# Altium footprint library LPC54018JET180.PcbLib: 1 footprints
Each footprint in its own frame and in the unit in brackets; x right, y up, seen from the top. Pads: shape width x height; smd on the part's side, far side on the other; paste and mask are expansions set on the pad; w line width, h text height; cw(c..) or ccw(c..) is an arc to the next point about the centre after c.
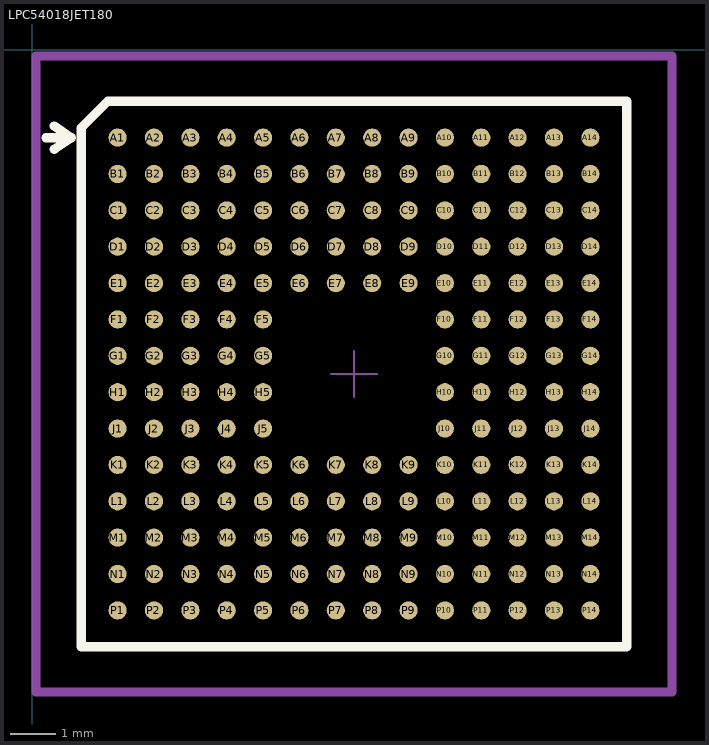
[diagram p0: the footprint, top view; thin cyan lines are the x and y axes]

## LPC54018JET180 [mm]
pads (180):
  round 0.4 smd: A1(1.876,-1.934) A2(2.676,-1.934) A3(3.476,-1.934) A4(4.276,-1.934) A5(5.076,-1.934) A6(5.876,-1.934) A7(6.676,-1.934) A8(7.476,-1.934) A9(8.276,-1.934) A10(9.076,-1.934) A11(9.876,-1.934) A12(10.676,-1.934) A13(11.476,-1.934) A14(12.276,-1.934) B1(1.876,-2.734) B2(2.676,-2.734) B3(3.476,-2.734) B4(4.276,-2.734) B5(5.076,-2.734) B6(5.876,-2.734) B7(6.676,-2.734) B8(7.476,-2.734) B9(8.276,-2.734) B10(9.076,-2.734) B11(9.876,-2.734) B12(10.676,-2.734) B13(11.476,-2.734) B14(12.276,-2.734) C1(1.876,-3.534) C2(2.676,-3.534) C3(3.476,-3.534) C4(4.276,-3.534) C5(5.076,-3.534) C6(5.876,-3.534) C7(6.676,-3.534) C8(7.476,-3.534) C9(8.276,-3.534) C10(9.076,-3.534) C11(9.876,-3.534) C12(10.676,-3.534) C13(11.476,-3.534) C14(12.276,-3.534) D1(1.876,-4.334) D2(2.676,-4.334) D3(3.476,-4.334) D4(4.276,-4.334) D5(5.076,-4.334) D6(5.876,-4.334) D7(6.676,-4.334) D8(7.476,-4.334) D9(8.276,-4.334) D10(9.076,-4.334) D11(9.876,-4.334) D12(10.676,-4.334) D13(11.476,-4.334) D14(12.276,-4.334) E1(1.876,-5.134) E2(2.676,-5.134) E3(3.476,-5.134) E4(4.276,-5.134) E5(5.076,-5.134) E6(5.876,-5.134) E7(6.676,-5.134) E8(7.476,-5.134) E9(8.276,-5.134) E10(9.076,-5.134) E11(9.876,-5.134) E12(10.676,-5.134) E13(11.476,-5.134) E14(12.276,-5.134) F1(1.876,-5.934) F2(2.676,-5.934) F3(3.476,-5.934) F4(4.276,-5.934) F5(5.076,-5.934) F10(9.076,-5.934) F11(9.876,-5.934) F12(10.676,-5.934) F13(11.476,-5.934) F14(12.276,-5.934) G1(1.876,-6.734) G2(2.676,-6.734) G3(3.476,-6.734) G4(4.276,-6.734) G5(5.076,-6.734) G10(9.076,-6.734) G11(9.876,-6.734) G12(10.676,-6.734) G13(11.476,-6.734) G14(12.276,-6.734) H1(1.876,-7.534) H2(2.676,-7.534) H3(3.476,-7.534) H4(4.276,-7.534) H5(5.076,-7.534) H10(9.076,-7.534) H11(9.876,-7.534) H12(10.676,-7.534) H13(11.476,-7.534) H14(12.276,-7.534) J1(1.876,-8.334) J2(2.676,-8.334) J3(3.476,-8.334) J4(4.276,-8.334) J5(5.076,-8.334) J10(9.076,-8.334) J11(9.876,-8.334) J12(10.676,-8.334) J13(11.476,-8.334) J14(12.276,-8.334) K1(1.876,-9.134) K2(2.676,-9.134) K3(3.476,-9.134) K4(4.276,-9.134) K5(5.076,-9.134) K6(5.876,-9.134) K7(6.676,-9.134) K8(7.476,-9.134) K9(8.276,-9.134) K10(9.076,-9.134) K11(9.876,-9.134) K12(10.676,-9.134) K13(11.476,-9.134) K14(12.276,-9.134) L1(1.876,-9.934) L2(2.676,-9.934) L3(3.476,-9.934) L4(4.276,-9.934) L5(5.076,-9.934) L6(5.876,-9.934) L7(6.676,-9.934) L8(7.476,-9.934) L9(8.276,-9.934) L10(9.076,-9.934) L11(9.876,-9.934) L12(10.676,-9.934) L13(11.476,-9.934) L14(12.276,-9.934) M1(1.876,-10.734) M2(2.676,-10.734) M3(3.476,-10.734) M4(4.276,-10.734) M5(5.076,-10.734) M6(5.876,-10.734) M7(6.676,-10.734) M8(7.476,-10.734) M9(8.276,-10.734) M10(9.076,-10.734) M11(9.876,-10.734) M12(10.676,-10.734) M13(11.476,-10.734) M14(12.276,-10.734) N1(1.876,-11.534) N2(2.676,-11.534) N3(3.476,-11.534) N4(4.276,-11.534) N5(5.076,-11.534) N6(5.876,-11.534) N7(6.676,-11.534) N8(7.476,-11.534) N9(8.276,-11.534) N10(9.076,-11.534) N11(9.876,-11.534) N12(10.676,-11.534) N13(11.476,-11.534) N14(12.276,-11.534) P1(1.876,-12.334) P2(2.676,-12.334) P3(3.476,-12.334) P4(4.276,-12.334) P5(5.076,-12.334) P6(5.876,-12.334) P7(6.676,-12.334) P8(7.476,-12.334) P9(8.276,-12.334) P10(9.076,-12.334) P11(9.876,-12.334) P12(10.676,-12.334) P13(11.476,-12.334) P14(12.276,-12.334)
Top Overlay:
  lines w0.2: 1.076,-13.134 13.076,-13.134 13.076,-1.134 1.66,-1.134 1.076,-1.718 1.076,-13.134
  lines w0.203: 0.302,-1.934 0.86,-1.934 ; 0.479,-2.188 0.86,-1.934 ; 0.479,-1.68 0.86,-1.934
Mechanical 15:
  lines w0.05: 6.576,-7.134 7.576,-7.134 ; 7.076,-7.634 7.076,-6.634
  lines w0.2: 0.076,-14.134 14.076,-14.134 14.076,-0.134 0.076,-0.134 0.076,-14.134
